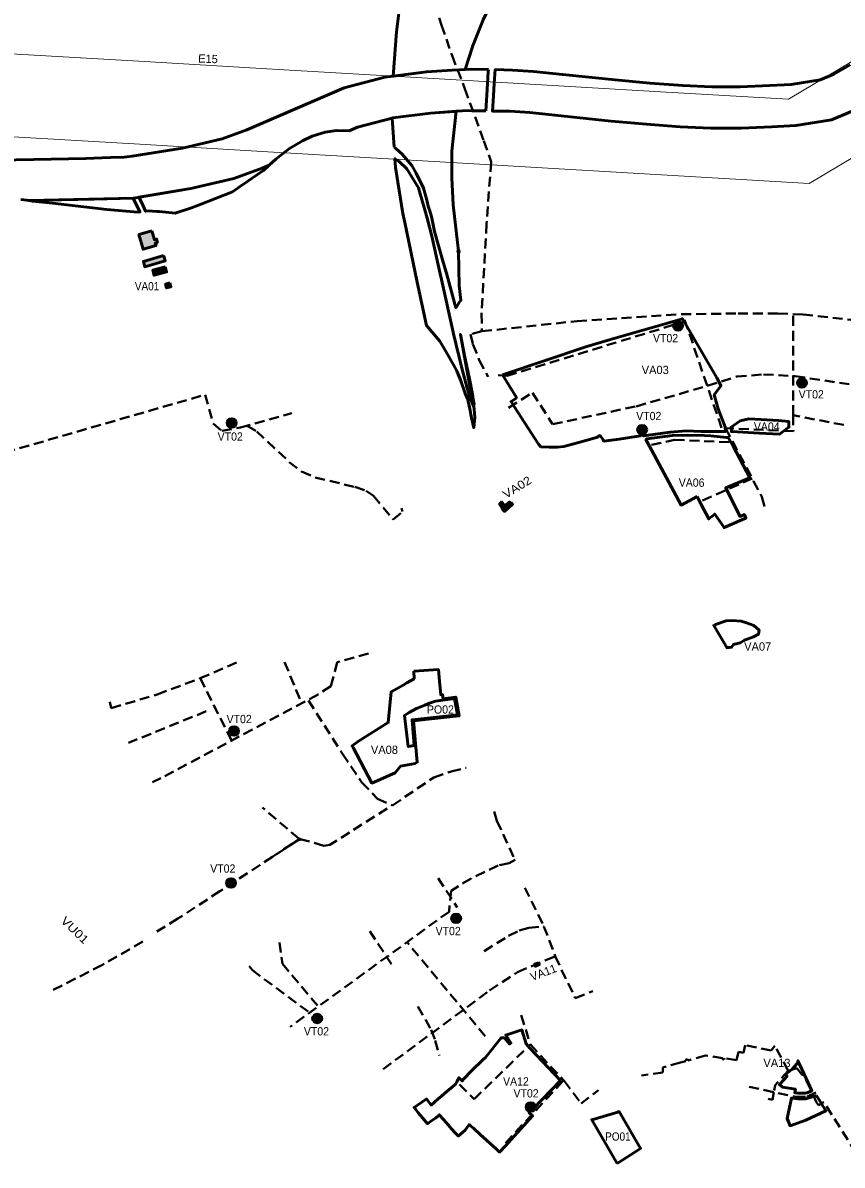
# Model space of a CAD drawing. Extents: x -650145 to -642675, y -1074338 to -1066724.
# Drawn here: x -648933 to -646953, y -1071599 to -1068839 of the extents above; entities that cross this region are included whole.
import ezdxf

# ---------------------------------------------------------------- set-up
doc = ezdxf.new("R2010")
doc.units = 0
doc.header["$LTSCALE"] = 8
doc.header["$PDMODE"] = 32
doc.header["$PDSIZE"] = 4
doc.linetypes.add('MEDIUM_DASHED', pattern=[4.5, 3, -1.5])
for name, color, linetype, lineweight in [('12', 7, 'MEDIUM_DASHED', 40), ('15', 7, 'Continuous', 13), ('20', 7, 'Continuous', 13), ('44', 7, 'Continuous', 53), ('45', 7, 'Continuous', 53), ('46', 7, 'Continuous', 53), ('60', 7, 'Continuous', 53)]:
    doc.layers.add(name, color=color, linetype=linetype, lineweight=lineweight)
for name, color, linetype in [('17', 7, 'Continuous'), ('2', 7, 'Continuous'), ('3', 7, 'Continuous'), ('4', 7, 'Continuous'), ('5', 7, 'Continuous')]:
    doc.layers.add(name, color=color, linetype=linetype)

msp = doc.modelspace()

# ---------------------------------------------------------------- hatches: boundary and pattern name
at = {"layer": '15'}
for points in [[(-647338.289, -1069571.583, 1), (-647361.814, -1069571.583, 1)], [(-647038.994, -1069709.305, 1), (-647062.519, -1069709.305, 1)], [(-648416.978, -1069806.101, 1), (-648440.503, -1069806.101, 1)], [(-647425.058, -1069822.133, 1), (-647448.583, -1069822.133, 1)], [(-648411.342, -1070550.264, 1), (-648434.867, -1070550.264, 1)], [(-648418.374, -1070917.603, 1), (-648441.898, -1070917.603, 1)], [(-647874.426, -1071003.073, 1), (-647897.951, -1071003.073, 1)], [(-648210.363, -1071245, 1), (-648233.888, -1071245, 1)], [(-647694.212, -1071458.99, 1), (-647717.737, -1071458.99, 1)]]:
    msp.add_hatch(color=256, dxfattribs=at).paths.add_polyline_path(points)
at = {"layer": '60'}
for points in [[(-648621.37, -1069342.03), (-648652.93, -1069350.8), (-648642.85, -1069386.53), (-648611.53, -1069377.7), (-648613.3, -1069371.42), (-648608.07, -1069369.95), (-648610.3, -1069362.04), (-648615.51, -1069363.51)], [(-648593.77, -1069401.82), (-648642.06, -1069415.98), (-648638.41, -1069428.97), (-648589.26, -1069414.15), (-648592.11, -1069405.18)], [(-648589.16, -1069429.3), (-648619.35, -1069437.29), (-648616.15, -1069449.33), (-648585.96, -1069441.33)], [(-648578.5, -1069467.6), (-648588.59, -1069470.49), (-648585.91, -1069479.97), (-648575.76, -1069477.15)], [(-647753.96, -1069997.9), (-647755.37, -1069999.17), (-647757.35, -1069996.96), (-647768.87, -1070007.32), (-647775.67, -1069996.86), (-647781.47, -1070001.96), (-647774.7, -1070012.64), (-647775.34, -1070013.22), (-647769.35, -1070019.98), (-647749.87, -1070002.45)], [(-647687.68, -1071110.18), (-647696.64, -1071114.02), (-647694.63, -1071118.73), (-647685.66, -1071114.89)]]:
    msp.add_hatch(color=256, dxfattribs=at).paths.add_polyline_path(points)

# ---------------------------------------------------------------- linework, layer by layer
at = {"layer": '12'}
for p, q in [((-647072.241, -1069787.533), (-647072.241, -1069543.185)), ((-647291.307, -1069993.228), (-647170.84, -1069940.165)), ((-648300.887, -1070383.875), (-648259.756, -1070483.608)), ((-648504.855, -1070423.103), (-648428.725, -1070573.36)), ((-648490.212, -1070502.827), (-648678.059, -1070578.955)), ((-648332.818, -1070855.794), (-648263.929, -1070810.849)), ((-647929.7, -1070905.7), (-647883.483, -1070976.724)), ((-647720.463, -1070929.111), (-647674.039, -1071022.323)), ((-648042.555, -1071114.098), (-648099.428, -1071026.867)), ((-647815.949, -1071287.658), (-648004.905, -1071060.503)), ((-647767.223, -1071546.187), (-647626.359, -1071394.366))]:
    msp.add_line(p, q, dxfattribs=at)
for points in [[(-648589.741, -1067377.342), (-648498.624, -1067558.559), (-648369.855, -1067814.661), (-648270.948, -1068007.281), (-648177.599, -1068195.293), (-648103.97, -1068344.741), (-648098.419, -1068348.539), (-648086.184, -1068375.018), (-648042.175, -1068501.421), (-647986.295, -1068657.442), (-647921.652, -1068844.799), (-647896.268, -1068918.371), (-647865.117, -1068998.629), (-647819.537, -1069124.409), (-647801.818, -1069175.256), (-647812.644, -1069324.711), (-647825.015, -1069541.552), (-647823.978, -1069584.663), (-647594.109, -1069559.949), (-647342.265, -1069543.531), (-647205.182, -1069541.582), (-647108.806, -1069541.669), (-647047.983, -1069544.191), (-646818.857, -1069568.917)], [(-646949.668, -1069811.025), (-647072.241, -1069787.533), (-647071.353, -1069826.293), (-647244.785, -1069818.042), (-647338.767, -1069543.481)], [(-647785.07, -1069690.63), (-647763.238, -1069692.321), (-647332.905, -1069560.606)], [(-647823.978, -1069584.663), (-647851.235, -1069591.7), (-647845.629, -1069616.01), (-647830.41, -1069654.06), (-647808.595, -1069694.89)], [(-647279.5, -1069716.624), (-647208.318, -1069694.158), (-647143.504, -1069688.843), (-647066.866, -1069693.057), (-646699.975, -1069748.527), (-646678.869, -1069753.112), (-646676.91, -1069743.82)], [(-647759.613, -1069769.184), (-647701.982, -1069733.103), (-647653.087, -1069809.089), (-647451.321, -1069765.984), (-647279.5, -1069716.624)], [(-649044.908, -1069897.057), (-648493.206, -1069738.027), (-648473.126, -1069807.804), (-648452.457, -1069825.52), (-648407.58, -1069817.388), (-648283.564, -1069782.827)], [(-648391.301, -1069812.851), (-648368.286, -1069826.694), (-648289.499, -1069900.443), (-648259.719, -1069923.17), (-648226.806, -1069937.698), (-648130.85, -1069960.81), (-648103.867, -1069970.198), (-648085.696, -1069982.585), (-648038.819, -1070039.248), (-648015.643, -1070020.009), (-648018.277, -1070012.103)], [(-647235.467, -1069818.485), (-647167.428, -1069946.59), (-647147.296, -1069984.626), (-647140.3, -1070010.7)], [(-647414.535, -1069859.089), (-647358.559, -1069846.998), (-647217.195, -1069852.888)], [(-648723.27, -1070480.1), (-648719.781, -1070495.186), (-648608.642, -1070462.104), (-648504.855, -1070423.103), (-648414.278, -1070383.546)], [(-648097.961, -1070362.859), (-648173.666, -1070383.828), (-648189.212, -1070442.001), (-648219.63, -1070462.294), (-648600.13, -1070664.406), (-648620.205, -1070674.13)], [(-648243.287, -1070476.499), (-648161.107, -1070605.619), (-648114.121, -1070674.786), (-648076.532, -1070713.851), (-648039.863, -1070730.017), (-647940.305, -1070662.397), (-647898.38, -1070648.071), (-647862.25, -1070638.96)], [(-648053, -1070737.9), (-648191.415, -1070825.487), (-648206.369, -1070827.623), (-648259.779, -1070812.134), (-648269.723, -1070814.735), (-648457.192, -1070937.393), (-648558.532, -1071003.71), (-648610.798, -1071035.598)], [(-648259.67, -1070812.106), (-648266.577, -1070810.067), (-648354.282, -1070735.576)], [(-647794.16, -1070745.19), (-647787.83, -1070767.157), (-647743.987, -1070862.016), (-647758.284, -1070869.702), (-647784.836, -1070875.103), (-647850.393, -1070906.456), (-647898.698, -1070936.31), (-647903.521, -1070987.043), (-648287.54, -1071265.293)], [(-647818.707, -1071082.607), (-647759.543, -1071045.17), (-647733.735, -1071032.504), (-647710.774, -1071025.971), (-647674.039, -1071022.323), (-647646.98, -1071094.735)], [(-648643.705, -1071059.314), (-648742.207, -1071116.062), (-648865.074, -1071178.477)], [(-648313.283, -1071061.443), (-648306.336, -1071112.945), (-648219.799, -1071215.376)], [(-648062.403, -1071367.342), (-647805.426, -1071176.999), (-647738.219, -1071133.017), (-647646.98, -1071094.735), (-647598.326, -1071195.826), (-647556.251, -1071178.604)], [(-648386.1, -1071118.4), (-648378.803, -1071128.097), (-648240.257, -1071231.033)], [(-647978.731, -1071216.254), (-647946.561, -1071272.093), (-647936.852, -1071298.253), (-647926.931, -1071334.225)], [(-647728.988, -1071237.115), (-647707.004, -1071307.776), (-647625.351, -1071395.71), (-647584.501, -1071450.177), (-647542.285, -1071418.425)], [(-647878.3, -1071404.7), (-647843.135, -1071439.808), (-647707.004, -1071307.776)], [(-647125.34, -1071322.14), (-647187.77, -1071309.47), (-647192.05, -1071327.84), (-647204.02, -1071325.39), (-647208.89, -1071345.24), (-647238.16, -1071341.03), (-647238.54, -1071343.71), (-647242.66, -1071343.12), (-647242.27, -1071340.44), (-647283.52, -1071334.51), (-647326.47, -1071346.51), (-647327.32, -1071343.47), (-647332.03, -1071344.79), (-647331.18, -1071347.82), (-647344.33, -1071351.49)], [(-647084.37, -1071371.2), (-647115.91, -1071311.35), (-647125.34, -1071322.14)], [(-647344.33, -1071351.49), (-647386.85, -1071363.37), (-647386.8, -1071375.58), (-647438.34, -1071382.93)], [(-647084.37, -1071371.2), (-647115.19, -1071405.75), (-647117.79, -1071418.96)], [(-646901.7, -1071599.29), (-646997.62, -1071446.82), (-647011, -1071454.09), (-647015.17, -1071448), (-647045.84, -1071382.28), (-647050.73, -1071380.13), (-647063.41, -1071364.59), (-647084.37, -1071371.2)], [(-647178.442, -1071409.986), (-647065.935, -1071434.456), (-647038.805, -1071433.925), (-647016.651, -1071423.819)], [(-647118.63, -1071423.24), (-647122.21, -1071441.39), (-647132.07, -1071439.37)]]:
    msp.add_lwpolyline(points, dxfattribs=at)
at = {"layer": '15', "lineweight": 35}
for centre in [(-647350.051, -1069571.583), (-647050.756, -1069709.305), (-648428.74, -1069806.101), (-647436.82, -1069822.133), (-648423.104, -1070550.264), (-648430.136, -1070917.603), (-647886.188, -1071003.073), (-648222.125, -1071245), (-647705.974, -1071458.99)]:
    msp.add_circle(centre, 11.762, dxfattribs=at)
at = {"layer": '20'}
for points in [[(-645696.222, -1068110.701), (-645999.704, -1068380.07), (-646264.963, -1068537.869), (-646558.558, -1068712.401), (-646840.473, -1068879.978), (-647082.853, -1069024.029), (-647392.269, -1069006.02), (-647721.495, -1068986.72), (-648010.52, -1068969.88), (-648329.902, -1068951.251), (-648639.277, -1068933.111), (-648948.071, -1068915.071), (-649057.05, -1068908.69), (-649199.47, -1069030.73), (-649232.77, -1069060.44), (-649258.79, -1069091.17), (-649263.719, -1069096.97)], [(-649263.719, -1069096.97), (-648650.963, -1069132.769), (-648341.578, -1069150.909), (-648022.16, -1069169.54), (-647733.165, -1069186.38), (-647403.931, -1069205.68), (-647033.327, -1069227.251), (-646738.287, -1069051.902)]]:
    msp.add_lwpolyline(points, dxfattribs=at)
at = {"layer": '44'}
for p, q in [((-648038.596, -1068968.281), (-647958.168, -1068957.73)), ((-647862.266, -1069668.613), (-647843.449, -1069768.252))]:
    msp.add_line(p, q, dxfattribs=at)
for points in [[(-647801.797, -1068219.34), (-647843.6, -1068292.629), (-647868.214, -1068337.803), (-647914.339, -1068432.512), (-647946.187, -1068510.254), (-647971.074, -1068581.98), (-647997.27, -1068674.747), (-648011.775, -1068739.718), (-648023.914, -1068809.332), (-648030.73, -1068861.213), (-648038.596, -1068968.281)], [(-647846.989, -1068896.545), (-647820.883, -1068832.117), (-647797.632, -1068784.713), (-647796.173, -1068782.191)], [(-647958.168, -1068957.73), (-647895.901, -1068953.392), (-647864.531, -1068951.823), (-647847.197, -1068897.199), (-647847.034, -1068896.687), (-647846.989, -1068896.545)], [(-647948.18, -1069057.276), (-648039.666, -1069069.279), (-648040.705, -1069069.548), (-648036.291, -1069139.458)], [(-647886.615, -1069053.052), (-647889.927, -1069053.218), (-647948.18, -1069057.276)], [(-647893.553, -1069279.017), (-647896.67, -1069213.573), (-647896.362, -1069149.171), (-647886.615, -1069053.052)], [(-648036.291, -1069139.458), (-648031.92, -1069142.67), (-648016.36, -1069156.54), (-647993.8, -1069184.11)], [(-648005.47, -1069192.09), (-648024.02, -1069174.7), (-648034.421, -1069167.61)], [(-648034.421, -1069167.61), (-648034.421, -1069167.61), (-648033, -1069189), (-648015, -1069300), (-648010.092, -1069322.087), (-647980.331, -1069465.915), (-647958.34, -1069570.699), (-647925.99, -1069608.57), (-647906.16, -1069641.48), (-647885.665, -1069678.788), (-647885.663, -1069678.794), (-647883.51, -1069682.71), (-647875.82, -1069701.85), (-647875.82, -1069701.85), (-647864.19, -1069735.12), (-647858.44, -1069749.43), (-647852.63, -1069775.7), (-647850.66, -1069785.74), (-647849.165, -1069793.367)], [(-648354.978, -1069190.492), (-648423.173, -1069215.44), (-648527.693, -1069239.938), (-648652.716, -1069260.657), (-648647.059, -1069272.723), (-648636.85, -1069294.49), (-648630.82, -1069293.63), (-648609.425, -1069295.033), (-648603.228, -1069295.53), (-648565.18, -1069299.46), (-648526.15, -1069286.21)], [(-648526.15, -1069286.21), (-648508.95, -1069280.01), (-648427.08, -1069247.75), (-648407.73, -1069233.88), (-648389.91, -1069221.86), (-648355.81, -1069198.88), (-648351.77, -1069195.88), (-648338.523, -1069183.389), (-648354.978, -1069190.492)], [(-647962.2, -1069290.88), (-647974.81, -1069246.86), (-647977.29, -1069238.21), (-648005.47, -1069192.09)], [(-647993.8, -1069184.11), (-647982.58, -1069202.33), (-647965.06, -1069238.95), (-647957.56, -1069264.74), (-647953.01, -1069285.73), (-647951.841, -1069289.09)], [(-647880.318, -1069391.297), (-647880.326, -1069390.832), (-647893.553, -1069279.017)], [(-647852.78, -1069745.71), (-647859.722, -1069722.428), (-647872.87, -1069673.56), (-647892.79, -1069591.06), (-647892.789, -1069591.06), (-647893.75, -1069587.08), (-647922.04, -1069459.71), (-647925.16, -1069445.68), (-647928.41, -1069431.03), (-647945.28, -1069355.1), (-647956.27, -1069311.58), (-647962.2, -1069290.88)], [(-647951.841, -1069289.09), (-647945.63, -1069306.95), (-647938.77, -1069343.17), (-647918.08, -1069417.43), (-647909.67, -1069444.46), (-647889.22, -1069519.32), (-647887.087, -1069527.229), (-647885.782, -1069525.389), (-647882.551, -1069520.835), (-647878.73, -1069515.45)], [(-647878.73, -1069515.45), (-647874.75, -1069509.84), (-647878.93, -1069475.09), (-647880.318, -1069391.297)], [(-647843.449, -1069768.252), (-647844.371, -1069761.991), (-647842.438, -1069760.647), (-647845.086, -1069748.753), (-647846.484, -1069736.663), (-647855.158, -1069695.232), (-647865.69, -1069647.32), (-647876.061, -1069592.206), (-647862.266, -1069668.613)], [(-647841.402, -1069792.351), (-647842.489, -1069773.282), (-647842.622, -1069770.956), (-647843.337, -1069769.013), (-647843.443, -1069768.293), (-647852.78, -1069745.71)], [(-647849.165, -1069793.367), (-647843.74, -1069817.63), (-647841.402, -1069792.351)]]:
    msp.add_lwpolyline(points, dxfattribs=at)
msp.add_lwpolyline([(-648730.66, -1069290.43), (-648655.53, -1069297.18), (-648650.06, -1069296.39), (-648650.58, -1069295.34), (-648662.417, -1069271.858), (-648666.827, -1069262.738), (-648761.189, -1069265.035), (-648918.889, -1069268.875), (-648909.86, -1069270.02), (-648861.49, -1069275.34), (-648785.92, -1069284.2), (-648730.66, -1069290.43)], close=True, dxfattribs=at)
msp.add_arc((-648354.978, -1069190.492), 0.000000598, 264.13978, 298.69712, dxfattribs=at)
msp.add_point((-647880.318, -1069391.297), dxfattribs=at)
at = {"layer": '45'}
for points in [[(-646934.465, -1068940.759), (-646973.61, -1068963.135), (-647006.63, -1068977.08), (-647076.422, -1068988.18), (-647128.674, -1068991.167), (-647199.672, -1068994.255), (-647268.348, -1068994.255), (-647338.816, -1068991.19), (-647417.895, -1068984.986), (-647502.412, -1068977.157), (-647629.424, -1068964.608), (-647699.561, -1068956.635), (-647749.978, -1068953.416), (-647792.01, -1068952.442), (-647794.21, -1068986.12), (-647796.13, -1069015.57), (-647798.631, -1069052.508), (-647756.441, -1069053.207), (-647708.401, -1069056.275), (-647511.94, -1069076.703), (-647426.417, -1069084.624), (-647344.902, -1069091.02), (-647270.522, -1069094.255), (-647197.498, -1069094.255), (-647123.648, -1069091.043), (-647065.688, -1069087.73), (-646978.92, -1069073.93), (-646929.186, -1069052.925)], [(-648038.759, -1068968.54), (-648038.746, -1068968.301), (-648058.764, -1068970.927), (-648156.739, -1068996.273), (-648392.002, -1069097.554), (-648451.865, -1069119.456), (-648547.243, -1069141.81), (-648668.959, -1069161.838), (-648688.912, -1069163.603), (-648721.315, -1069164.952), (-648781.015, -1069167.44), (-649076.02, -1069172.683)], [(-647864.531, -1068951.823), (-647895.901, -1068953.392), (-647958.168, -1068957.73), (-648038.596, -1068968.281), (-648038.759, -1068968.54)], [(-647808.28, -1068952.066), (-647850.043, -1068951.098), (-647864.531, -1068951.823)], [(-647814.401, -1069052.246), (-647812.34, -1069014.54), (-647808.67, -1068958.06), (-647808.28, -1068952.066)], [(-648040.705, -1069069.547), (-648039.666, -1069069.279), (-647948.18, -1069057.276), (-647886.615, -1069053.052), (-647856.541, -1069051.548), (-647848.615, -1069051.679), (-647842.888, -1069051.774), (-647814.401, -1069052.246)], [(-648937.91, -1069266.51), (-648924.13, -1069268.21), (-648918.889, -1069268.875), (-648665.007, -1069262.694), (-648527.693, -1069239.938), (-648423.173, -1069215.44), (-648354.978, -1069190.492), (-648338.523, -1069183.389), (-648322.14, -1069168.56), (-648306.83, -1069156.57), (-648289.25, -1069142.79), (-648257.5, -1069124.41), (-648234.22, -1069113.6), (-648202.46, -1069103.3), (-648175.65, -1069099.64), (-648144.866, -1069099.987), (-648124.327, -1069091.181), (-648040.705, -1069069.547)]]:
    msp.add_lwpolyline(points, dxfattribs=at)
at = {"layer": '46'}
for points in [[(-647883.383, -1070511.163), (-647889.978, -1070472.005), (-647936.144, -1070478.187), (-647950.48, -1070482.79), (-647962.184, -1070487.748), (-647981.81, -1070496.06), (-647999.756, -1070505.655), (-648010.831, -1070512.588), (-648002, -1070588), (-647987.667, -1070585.565), (-647992.819, -1070523.117)], [(-647497.04, -1071595.66), (-647440.67, -1071558.93), (-647492.3, -1071470), (-647495.85, -1071471.06), (-647558.654, -1071489.738)]]:
    msp.add_lwpolyline(points, close=True, dxfattribs=at)
at = {"layer": '60'}
for points in [[(-648621.37, -1069342.03), (-648652.93, -1069350.8), (-648642.85, -1069386.53), (-648611.53, -1069377.7), (-648613.3, -1069371.42), (-648608.07, -1069369.95), (-648610.3, -1069362.04), (-648615.51, -1069363.51)], [(-648593.77, -1069401.82), (-648642.06, -1069415.98), (-648638.41, -1069428.97), (-648589.26, -1069414.15), (-648592.11, -1069405.18)], [(-648589.16, -1069429.3), (-648619.35, -1069437.29), (-648616.15, -1069449.33), (-648585.96, -1069441.33)], [(-648578.5, -1069467.6), (-648588.59, -1069470.49), (-648585.91, -1069479.97), (-648575.76, -1069477.15)], [(-647774.11, -1069689.64), (-647740.74, -1069744.24), (-647742.36, -1069746.93), (-647753.7, -1069753.9), (-647745.84, -1069766.71), (-647687.45, -1069857.15), (-647681.51, -1069863.72), (-647661.79, -1069864.92), (-647641.78, -1069864.26), (-647625.83, -1069863.19), (-647593.07, -1069853.74), (-647572.63, -1069848.63), (-647547.12, -1069840.87), (-647538.34, -1069836.68), (-647531.33, -1069847.23), (-647529.5, -1069849.99), (-647492.76, -1069845.02), (-647441.19, -1069837.6), (-647437.46, -1069832.27), (-647433.32, -1069837.33), (-647369.3, -1069828.22), (-647330.46, -1069825.51), (-647294.38, -1069826.88), (-647270.09, -1069827.02), (-647253.88, -1069827.12), (-647236.5, -1069826.63), (-647235.49, -1069826.51), (-647235.62, -1069817.62), (-647253.45, -1069771.95), (-647262.46, -1069738.25), (-647253.97, -1069726.27), (-647247.86, -1069717.66), (-647246.42, -1069715.63), (-647256.061, -1069697.32), (-647339.58, -1069554.46), (-647375.71, -1069564.91), (-647499.63, -1069600.73), (-647570.37, -1069621.18)], [(-647178.73, -1069796.4), (-647199.65, -1069800.69), (-647221.87, -1069816.21), (-647221.14, -1069826.761), (-647153.36, -1069830.79), (-647104.741, -1069833.568), (-647082.145, -1069816.321), (-647082.206, -1069802.916), (-647107.04, -1069799.84), (-647148.9, -1069797.88)], [(-647304.05, -1069983.79), (-647294.257, -1070002.745), (-647276, -1070038.08), (-647261.27, -1070026.12), (-647238.99, -1070059.05), (-647195.933, -1070040.107), (-647186.148, -1070035.802), (-647186.4, -1070035.27), (-647189.83, -1070027.59), (-647199.984, -1070032.112), (-647229.096, -1069974.658), (-647235, -1069963), (-647176.499, -1069938.333), (-647217.177, -1069862.57), (-647228.77, -1069840.98), (-647232.66, -1069841.07), (-647270.71, -1069837.61), (-647285.9, -1069836.66), (-647326.71, -1069835.46), (-647363.21, -1069836.64), (-647425.73, -1069844.31), (-647427.62, -1069845.94), (-647413.461, -1069872.442), (-647342.93, -1070004.49)], [(-647753.96, -1069997.9), (-647755.37, -1069999.17), (-647757.35, -1069996.96), (-647768.87, -1070007.32), (-647775.67, -1069996.86), (-647781.47, -1070001.96), (-647774.7, -1070012.64), (-647775.34, -1070013.22), (-647769.35, -1070019.98), (-647749.87, -1070002.45)], [(-647219.36, -1070283.36), (-647233.82, -1070284.22), (-647259.22, -1070292.91), (-647263.72, -1070295.43), (-647232.55, -1070348.65), (-647226.24, -1070348.88), (-647220.9, -1070348.04), (-647216.16, -1070340.99), (-647199.79, -1070337.21), (-647189.63, -1070330.53), (-647167.43, -1070322.66), (-647155.89, -1070316.51), (-647154.23, -1070306.63), (-647167.15, -1070295.69), (-647184.77, -1070288.73), (-647197.68, -1070285.3)], [(-647988.86, -1070405.95), (-647988.11, -1070423.93), (-648005.668, -1070434.145), (-648014.63, -1070439.36), (-648043.43, -1070456.12), (-648050.38, -1070530.2), (-648122.57, -1070575), (-648137.78, -1070586.25), (-648135.47, -1070590.61), (-648098.637, -1070659.682), (-648089.82, -1070676.22), (-648033.29, -1070651.18), (-648020.51, -1070635.05), (-647985.44, -1070629.07), (-647980.2, -1070625.7), (-647989.5, -1070525.73), (-647901.695, -1070516.259), (-647879.16, -1070513.83), (-647887.08, -1070468.54), (-647917.98, -1070472.47), (-647918.95, -1070462.36), (-647923.53, -1070462.75), (-647926.53, -1070429.76), (-647929.24, -1070401.97)], [(-647687.68, -1071110.18), (-647696.64, -1071114.02), (-647694.63, -1071118.73), (-647685.66, -1071114.89)], [(-647777.4, -1071291.32), (-647777.4, -1071291.32), (-647774.14, -1071291.34), (-647769.85, -1071291.91), (-647756.67, -1071306.77), (-647753.89, -1071303.94), (-647766.35, -1071285.11), (-647727.368, -1071272.362), (-647717.363, -1071306.29), (-647708.429, -1071316.821), (-647634.524, -1071394.901), (-647700.078, -1071462.96), (-647710.546, -1071472.023), (-647704.78, -1071477.1), (-647701.415, -1071480.15), (-647708.18, -1071487.57), (-647767.575, -1071553.083), (-647781.31, -1071567.79), (-647789.73, -1071560.1), (-647828.024, -1071525.256), (-647844.4, -1071510.2), (-647850.55, -1071505.14), (-647855.23, -1071501.297), (-647860.576, -1071508.843), (-647864.69, -1071514.65), (-647869.922, -1071519.269), (-647876.29, -1071524.89), (-647881.16, -1071529.25), (-647883.31, -1071526.83), (-647889.29, -1071520.11), (-647897.27, -1071511.15), (-647905.25, -1071502.19), (-647917.23, -1071488.75), (-647927.2, -1071477.54), (-647929.26, -1071480.77), (-647931.17, -1071482.12), (-647936.59, -1071485.96), (-647944.81, -1071491.78), (-647955.14, -1071499.23), (-647967.13, -1071486.01), (-647972.76, -1071479), (-647977.13, -1071474.05), (-647984.07, -1071465.1), (-647987.8, -1071459.68), (-647961.4, -1071441.47), (-647957.906, -1071439.06), (-647946.78, -1071454.23), (-647937.43, -1071446.16), (-647930.38, -1071440.08), (-647921.96, -1071432.81), (-647913.31, -1071425.35), (-647904.3, -1071417.58), (-647895.29, -1071409.81), (-647888.11, -1071403.61), (-647885.05, -1071397.88), (-647879.76, -1071387.96), (-647871.68, -1071395.59), (-647867.45, -1071390.95), (-647849.86, -1071372.18), (-647820.93, -1071344.25), (-647815.474, -1071339.22)], [(-647056.48, -1071355.32), (-647060.6, -1071346.87), (-647060.22, -1071349.87), (-647061.4, -1071352.51), (-647062.78, -1071354.77), (-647073.68, -1071366.75), (-647075.25, -1071368.01), (-647083.48, -1071374.62), (-647090.04, -1071379.44), (-647088.57, -1071381.97), (-647086.45, -1071384.59), (-647105.2, -1071404.54), (-647097.5, -1071410.96), (-647066.35, -1071415.79), (-647068.162, -1071424.298), (-647061.23, -1071425.434), (-647043.137, -1071424.978), (-647038.119, -1071424.37), (-647026.472, -1071419.614), (-647035.47, -1071400.31)], [(-647015.484, -1071430.864), (-647040.878, -1071438.769), (-647060.532, -1071439.002), (-647076.037, -1071437.073), (-647086.716, -1071486.782), (-647079.168, -1071503.954), (-647040.889, -1071490.395), (-646992.555, -1071467.975)]]:
    msp.add_lwpolyline(points, close=True, dxfattribs=at)

# ---------------------------------------------------------------- texts
at = {"layer": '17', "width": 0.95}
for p in [(-647410.59, -1069611.16), (-647058.579, -1069746.971), (-647451.166, -1069799.33), (-648462.628, -1069848.885), (-648441.04, -1070531.428), (-648480.548, -1070892.65), (-647935.934, -1071043.636), (-648254.236, -1071285.892), (-647747.641, -1071435.784)]:
    msp.add_text('VT02', height=20, dxfattribs=at).set_placement(p)
at = {"layer": '2', "width": 1.2}
msp.add_text('VU01', height=20, rotation=315.876, dxfattribs=at).set_placement((-648843.543, -1071010.613))
at = {"layer": '20'}
msp.add_text('E15', height=20, rotation=357.579, dxfattribs=at).set_placement((-648510.172, -1068935.14))
at = {"layer": '3'}
for s, width, p in [('VA01', 0.9, (-648662.691, -1069485.662)), ('VA04', 0.95, (-647166.855, -1069824.823)), ('VA06', 0.95, (-647348.354, -1069960.268)), ('VA12', 0.95, (-647772.908, -1071406.958))]:
    msp.add_text(s, height=20, dxfattribs=dict(at, width=width)).set_placement(p)
for s, p in [('VA03', (-647437.904, -1069687.886)), ('VA07', (-647190.33, -1070356.214)), ('VA08', (-648092.311, -1070605.712)), ('VA13', (-647143.769, -1071362.286))]:
    msp.add_text(s, height=20, dxfattribs=at).set_placement(p)
at = {"layer": '3', "width": 1.15}
msp.add_text('VA02', height=20, rotation=31.795, dxfattribs=at).set_placement((-647765.887, -1069989.737))
at = {"layer": '3'}
msp.add_text('VA11', height=20, rotation=20.894, dxfattribs=at).set_placement((-647702.554, -1071154.847))
at = {"layer": '4', "width": 0.9}
msp.add_text('PO01', height=20, dxfattribs=at).set_placement((-647526.167, -1071540.041))
at = {"layer": '5', "width": 0.95}
msp.add_text('PO02', height=20, dxfattribs=at).set_placement((-647956.859, -1070508.429))

doc.saveas('drawing.dxf')
